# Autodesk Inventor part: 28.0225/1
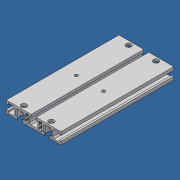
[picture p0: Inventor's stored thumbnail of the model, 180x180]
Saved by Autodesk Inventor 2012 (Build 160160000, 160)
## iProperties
Created: 2007-06
Part Number: 28.0225/1
Material: Aluminum-6061
Document SubType Name: Modeling
Designer: Andy Moles
Density: 2.71 g/cm^3
Mass: 357.424 g
Surface Area: 895.125 cm^2
Volume: 131.891 cm^3
Stock Number: 20.0995 PROFILE 90X19
Vendor: F
Description: L = 7.283", MILL TO 28.0225/1
Author: Andy Moles
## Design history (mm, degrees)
sketch "Sketch1"
  geometry: L1 (18.4, -9.5)-(18.4, -5) reference; L2 (17.9, -5)-(15.7, -5) reference; L3 (15.7, -5)-(15.7, 3.5) reference; L4 (15.7, 3.5)-(18, 5.8) reference; L5 (18, 5.8)-(27, 5.8) reference; L6 (27, 5.8)-(29.3, 3.5) reference; L7 (29.3, 3.5)-(29.3, -5) reference; L8 (26.6, -5)-(26.6, -9.5) reference; L9 (45, -9.5)-(26.9, -9.5) reference; L10 (45, -4.1)-(45, -9.5) reference; L11 (45, -4.1)-(42, -4.1) reference; L12 (42, -4.6)-(42, -6.8) reference; L13 (42, -6.8)-(33.5, -6.8) reference; L14 (33.5, -6.8)-(31.2, -4.5) reference; L15 (31.2, -4.5)-(31.2, 4.5) reference; L16 (31.2, 4.5)-(33.5, 6.8) reference; L17 (33.5, 6.8)-(42, 6.8) reference; L18 (42, 4.1)-(45, 4.1) reference; L19 (45, 9.5)-(45, 4.1) reference; L20 (4.4, 9.5)-(45, 9.5) reference; L21 (4.1, 9.5)-(4.1, 5) reference; L22 (4.6, 5)-(6.8, 5) reference; L23 (6.8, 5)-(6.8, -3.5) reference; L24 (6.8, -3.5)-(4.5, -5.8) reference; L25 (4.5, -5.8)-(-4.5, -5.8) reference; L26 (-4.5, -5.8)-(-6.8, -3.5) reference; L27 (-6.8, -3.5)-(-6.8, 5) reference; L28 (-4.1, 5)-(-4.1, 9.5) reference; L29 (-45, 4.1)-(-45, 9.5) reference; L30 (-45, 4.1)-(-42, 4.1) reference; L31 (-42, 4.1)-(-42, 6.8) reference; L32 (-42, 6.8)-(-33.5, 6.8) reference; L33 (-33.5, 6.8)-(-31.2, 4.5) reference; L34 (-31.2, 4.5)-(-31.2, -4.5) reference; L35 (-31.2, -4.5)-(-33.5, -6.8) reference; L36 (-33.5, -6.8)-(-42, -6.8) reference; L37 (-42, -6.8)-(-42, -4.1) reference; L38 (-42, -4.1)-(-45, -4.1) reference; L39 (-45, -9.5)-(-45, -4.1) reference; L40 (-26.6, -9.5)-(-26.6, -5) reference; L41 (-29.3, -5)-(-29.3, 3.5) reference; L42 (-29.3, 3.5)-(-27, 5.8) reference; L43 (-27, 5.8)-(-18, 5.8) reference; L44 (-18, 5.8)-(-15.7, 3.5) reference; L45 (-15.7, 3.5)-(-15.7, -5) reference; L46 (-15.7, -5)-(-17.9, -5) reference; L47 (-18.4, -5)-(-18.4, -9.5) reference; L48 (-18.1, -9.5)-(-18.4, -9.5) reference; L49 (-26.6, -9.5)-(-45, -9.5) reference; L50 (-17.9, -5)-(-18.4, -5) reference; L51 (-26.6, -5)-(-29.3, -5) reference; L52 (-6.8, 5)-(-4.1, 5) reference; L53 (4.1, 5)-(4.6, 5) reference; L54 (-45, 9.5)-(-4.1, 9.5) reference; L55 (4.1, 9.5)-(4.4, 9.5) reference; L56 (29.3, -5)-(26.6, -5) reference; L57 (18.4, -5)-(17.9, -5) reference; L58 (26.9, -9.5)-(26.6, -9.5) reference; L59 (18.4, -9.5)-(-18.1, -9.5) reference; L60 (42, 6.8)-(42, 4.1) reference; L61 (42, -4.1)-(42, -4.6) reference; L62 (13.3, 5)-(13.3, 3.657); L63 (13.007, 2.95)-(12.646, 2.59); L64 (10.7, 7)-(11.3, 7)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; A1 r 1 centre (12.3, 3.657) between (13.007, 2.95) and (13.3, 3.657); A2 r 0.5 centre (13, 2.236) between (12.646, 2.59) and (12.667, 1.863); A3 r 2 centre (11.3, 5) between (13.3, 5) and (11.3, 7); A4 r 0.5 centre (9, 2.236) between (9.333, 1.863) and (9.354, 2.59); A5 r 1 centre (9.7, 3.657) between (8.7, 3.657) and (8.993, 2.95); A6 r 2 centre (10.7, 5) between (10.7, 7) and (8.7, 5); A7 r 1 centre (9.7, -3.657) between (8.993, -2.95) and (8.7, -3.657); A8 r 2.5 centre (11, 0) between (9.333, 1.863) and (9.333, -1.863); A9 r 0.5 centre (9, -2.236) between (9.354, -2.59) and (9.333, -1.863); A10 r 2 centre (10.7, -5) between (8.7, -5) and (10.7, -7); A11 r 2.5 centre (11, 0) between (12.667, -1.863) and (12.667, 1.863); A12 r 0.5 centre (13, -2.236) between (12.667, -1.863) and (12.646, -2.59); A13 r 1 centre (12.3, -3.657) between (13.3, -3.657) and (13.007, -2.95); A14 r 2 centre (11.3, -5) between (11.3, -7) and (13.3, -5); A15 r 2.5 centre (-11, 0) between (-9.333, -1.863) and (-9.333, 1.863); A16 r 1 centre (-9.7, -3.657) between (-8.7, -3.657) and (-8.993, -2.95); A17 r 2 centre (-10.7, -5) between (-10.7, -7) and (-8.7, -5); A18 r 0.5 centre (-9, -2.236) between (-9.333, -1.863) and (-9.354, -2.59); A19 r 1 centre (-12.3, -3.657) between (-13.007, -2.95) and (-13.3, -3.657); A20 r 2.5 centre (-11, 0) between (-12.667, 1.863) and (-12.667, -1.863); A21 r 2 centre (-11.3, -5) between (-13.3, -5) and (-11.3, -7); A22 r 0.5 centre (-13, -2.236) between (-12.646, -2.59) and (-12.667, -1.863); A23 r 0.5 centre (-13, 2.236) between (-12.667, 1.863) and (-12.646, 2.59); A24 r 2 centre (-11.3, 5) between (-11.3, 7) and (-13.3, 5); A25 r 0.5 centre (-9, 2.236) between (-9.354, 2.59) and (-9.333, 1.863); A26 r 1 centre (-9.7, 3.657) between (-8.993, 2.95) and (-8.7, 3.657); A27 r 2 centre (-10.7, 5) between (-8.7, 5) and (-10.7, 7); A28 r 1 centre (-12.3, 3.657) between (-13.3, 3.657) and (-13.007, 2.95)
  constraints: 162 end point, 56 point on circle, 28 centre point, 28 horizontal, 23 vertical, 71 other
extrude "Extrusion1" new body sketch "Sketch1" stored distance "d0" = 185; taper "d1" = 0 deg
sketch "Sketch2"
  geometry: L1 (0, -185)-(36.8, -185) reference; L2 (63.4, -185)-(63.4, 0) reference; 6 further points
  constraints: 2 horizontal alignment, 2 vertical alignment
  dimensions: "d2" = 185 distance of L1.end point (36.8, 0) (derived); "d3" = 172 distance of point (40.9, -178.5) point (40.9, -6.5); "d4" = 6.5 distance from line of point (40.9, -178.5) L1 (= -0.5 x d3 + 0.5 x d2); "d5" = 22.5 distance from line of point (40.9, -6.5) L2; "d6" = 67.5 distance from line of point (-4.1, -6.5) L2
hole "Hole1" sketch "Sketch2" at (40.9, -6.5), (-4.1, -6.5), (-4.1, -178.5), (40.9, -178.5) diameter "d7" = 9; stored, may be unused: countersink angle "d11" = 90 deg, drill point angle "d13" = 118 deg; dims "d8" = 6, "d9" = 15, "d10" = 15.3, "d12" = 8
sketch "Sketch3"
  geometry: 3 further points
  constraints: 2 horizontal alignment
  dimensions: "d14" = 22.5 distance of point (40.9, -92.5) point (18.4, -92.5); "d15" = 22.5 distance of point (-4.1, -92.5) point (18.4, -92.5)
hole "Hole2" sketch "Sketch3" at (40.9, -92.5), (-4.1, -92.5) diameter "d16" = 5.5; stored, may be unused: countersink angle "d20" = 90 deg, drill point angle "d22" = 118 deg; dims "d17" = 6, "d18" = 9, "d19" = 15.3, "d21" = 8
body "Solid1"
